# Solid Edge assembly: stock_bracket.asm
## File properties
Author: Deepak Maini
Template: Normal.asm
Last saved by: CADCIM
Revision: 28
Application: Solid Edge
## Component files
adjusting_screw_nut.par
support_adjusting_screw.par
support_roller_bracket.par
stock_support_roller.par
adjusting_nut_handle.par
adjusting_screw_guide.par
Stock_support_base.par
thrust_bearing.par
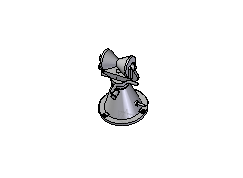
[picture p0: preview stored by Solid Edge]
